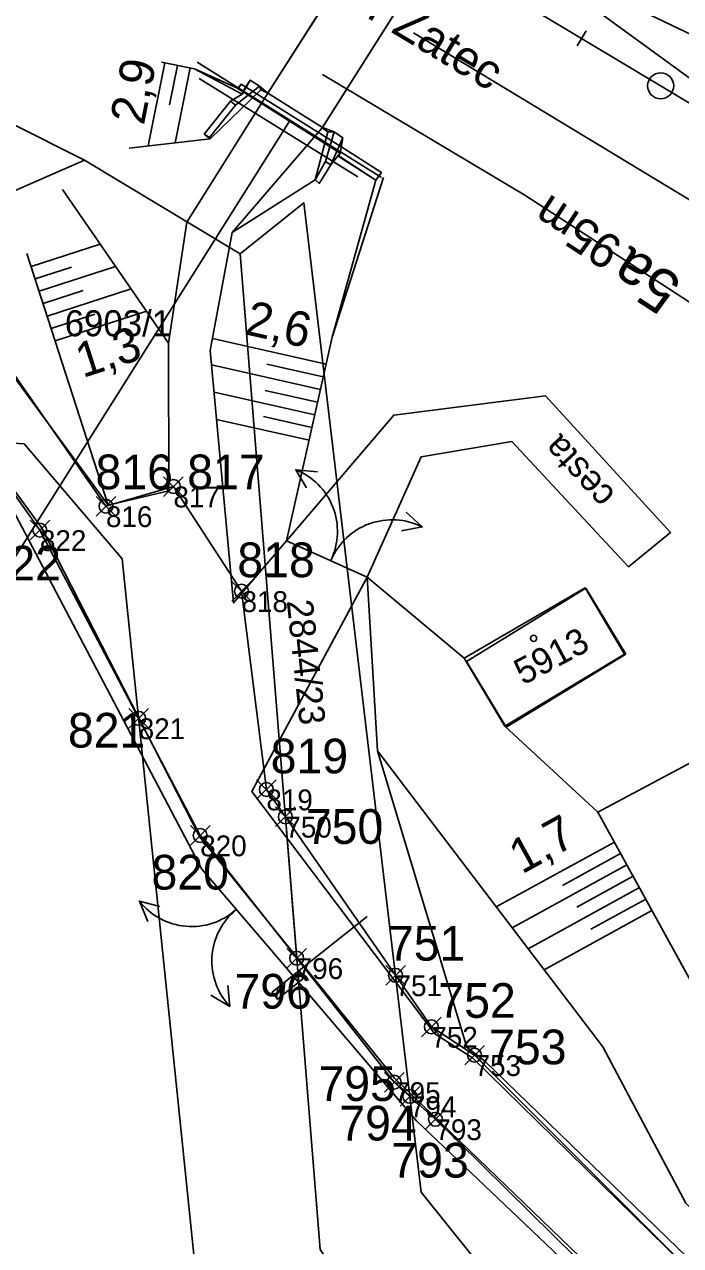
# Model space of a CAD drawing. Extents: x -800194 to -799078, y -1007177 to -1006597.
# Drawn here: x -799843.2 to -799805.4, y -1007023.9 to -1006953.5 of the extents above; entities that cross this region are included whole.
import ezdxf

# ---------------------------------------------------------------- set-up
doc = ezdxf.new("R2010")
doc.units = 0
for name, color, linetype in [('02_Osa_koleje', 7, 'Continuous'), ('_návrh', 7, 'Continuous'), ('Dočasné zábory', 7, 'Continuous'), ('Obvod stavby', 7, 'Continuous'), ('Vrstva 1', 7, 'Continuous'), ('Vrstva 17', 7, 'Continuous'), ('Vrstva 18', 7, 'Continuous'), ('Vrstva 2', 7, 'Continuous'), ('Vrstva 23', 7, 'Continuous'), ('Vrstva 4', 7, 'Continuous'), ('Vrstva 45', 7, 'Continuous'), ('Vrstva 48', 7, 'Continuous'), ('Vrstva 49', 7, 'Continuous'), ('Vrstva 51', 7, 'Continuous'), ('Vrstva 53', 7, 'Continuous'), ('Vrstva 55', 7, 'Continuous'), ('Vrstva 57', 7, 'Continuous'), ('Vrstva 59', 7, 'Continuous'), ('Vrstva 60', 7, 'Continuous'), ('Vrstva 7', 7, 'Continuous')]:
    doc.layers.add(name, color=color, linetype=linetype)

msp = doc.modelspace()

# ---------------------------------------------------------------- linework, layer by layer
at = {"layer": '_návrh'}
for p, q in [((-799820.103, -1006945.483), (-799793.935, -1006964.581)), ((-799791.771, -1006960.349), (-799809.481, -1006951.835))]:
    msp.add_line(p, q, dxfattribs=at)
for points in [[(-799821.595, -1006948.007), (-799811.064, -1006954.324), (-799803.753, -1006958.707), (-799793.935, -1006964.581), (-799784.224, -1006971.671), (-799782.913, -1006972.63), (-799767.418, -1006984.719), (-799752.333, -1006998.173), (-799735.027, -1007015.997), (-799721.623, -1007030.81), (-799713.555, -1007039.726), (-799713.111, -1007040.218)], [(-799820.755, -1006954.001), (-799803.004, -1006964.743), (-799786.682, -1006975.322), (-799769.882, -1006987.807), (-799754.745, -1007000.643), (-799736.311, -1007017.261), (-799721.623, -1007030.81)]]:
    msp.add_lwpolyline(points, dxfattribs=at)
at = {"layer": 'Dočasné zábory'}
for p, q in [((-799835.159, -1006980.715), (-799834.028, -1006979.584)), ((-799835.159, -1006979.584), (-799834.028, -1006980.715)), ((-799839.05, -1006981.851), (-799837.918, -1006980.719)), ((-799839.05, -1006980.719), (-799837.918, -1006981.851)), ((-799842.856, -1006983.229), (-799841.725, -1006982.097)), ((-799842.856, -1006982.097), (-799841.725, -1006983.229)), ((-799831.237, -1006986.747), (-799830.105, -1006985.615)), ((-799831.237, -1006985.615), (-799830.105, -1006986.747)), ((-799837.161, -1006994.075), (-799836.029, -1006992.943)), ((-799837.161, -1006992.943), (-799836.029, -1006994.075)), ((-799829.802, -1006998.175), (-799828.671, -1006997.044)), ((-799829.802, -1006997.044), (-799828.671, -1006998.175)), ((-799833.617, -1007000.824), (-799832.485, -1006999.692)), ((-799833.617, -1006999.692), (-799832.485, -1007000.824))]:
    msp.add_line(p, q, dxfattribs=at)
for points in [[(-799967.931, -1006901.133), (-799932.438, -1006916.61), (-799908.959, -1006929.954), (-799851.516, -1006962.598), (-799849.434, -1006965.582), (-799838.484, -1006981.285), (-799834.593, -1006980.15), (-799830.671, -1006986.181), (-799829.237, -1006997.609), (-799828.144, -1006999.182)], [(-799827.489, -1007007.333), (-799833.051, -1007000.258), (-799836.595, -1006993.509), (-799842.29, -1006982.663), (-799845.937, -1006977.529), (-799850.111, -1006971.653), (-799853.923, -1006967.549), (-799855.042, -1006966.345), (-799901.914, -1006939.708), (-799934.679, -1006921.088), (-799969.583, -1006905.867)]]:
    msp.add_lwpolyline(points, dxfattribs=at)
for centre in [(-799834.593, -1006980.15), (-799838.484, -1006981.285), (-799842.29, -1006982.663), (-799830.671, -1006986.181), (-799836.595, -1006993.509), (-799829.237, -1006997.609), (-799833.051, -1007000.258)]:
    msp.add_circle(centre, 0.4, dxfattribs=at)
at = {"layer": 'Obvod stavby'}
for p, q in [((-799828.709, -1006999.748), (-799827.578, -1006998.616)), ((-799828.709, -1006998.616), (-799827.578, -1006999.748)), ((-799828.055, -1007007.899), (-799826.923, -1007006.767)), ((-799828.055, -1007006.767), (-799826.923, -1007007.899)), ((-799822.359, -1007008.885), (-799821.227, -1007007.753)), ((-799822.359, -1007007.753), (-799821.227, -1007008.885)), ((-799820.294, -1007011.855), (-799819.163, -1007010.723)), ((-799820.294, -1007010.723), (-799819.163, -1007011.855)), ((-799817.801, -1007013.487), (-799816.67, -1007012.355)), ((-799817.801, -1007012.355), (-799816.67, -1007013.487)), ((-799822.436, -1007015.046), (-799821.304, -1007013.915)), ((-799822.436, -1007013.915), (-799821.304, -1007015.046)), ((-799821.531, -1007015.86), (-799820.399, -1007014.729)), ((-799821.531, -1007014.729), (-799820.399, -1007015.86)), ((-799820.06, -1007017.183), (-799818.929, -1007016.051)), ((-799820.06, -1007016.051), (-799818.929, -1007017.183))]:
    msp.add_line(p, q, dxfattribs=at)
for points in [[(-799820.965, -1007015.295), (-799821.87, -1007014.48), (-799827.489, -1007007.333), (-799828.144, -1006999.182), (-799821.793, -1007008.319)], [(-799788.573, -1007041.596), (-799817.235, -1007012.921), (-799819.729, -1007011.289), (-799821.793, -1007008.319)], [(-799820.965, -1007015.295), (-799819.494, -1007016.617), (-799797.841, -1007037.951)]]:
    msp.add_lwpolyline(points, dxfattribs=at)
for centre in [(-799828.144, -1006999.182), (-799827.489, -1007007.333), (-799821.793, -1007008.319), (-799819.729, -1007011.289), (-799817.235, -1007012.921), (-799821.87, -1007014.48), (-799820.965, -1007015.295), (-799819.494, -1007016.617)]:
    msp.add_circle(centre, 0.4, dxfattribs=at)
at = {"layer": 'Vrstva 1'}
msp.add_lwpolyline([(-799773.482, -1006996.72), (-799784.684, -1006984.939), (-799796.383, -1006975.181), (-799798.809, -1006973.435), (-799814.345, -1006963.355), (-799826.008, -1006956.394)], dxfattribs=at)
at = {"layer": 'Vrstva 17'}
for p, q in [((-799822.595, -1006962.333), (-799833.226, -1006955.692)), ((-799823.433, -1006985.376), (-799828.082, -1006983.271)), ((-799817.838, -1006990.049), (-799823.433, -1006985.376)), ((-799810.13, -1006998.908), (-799815.5, -1006993.967)), ((-799832.962, -1007002.208), (-799828.95, -1007006.881))]:
    msp.add_line(p, q, dxfattribs=at)
for points in [[(-799828.082, -1006983.271), (-799825.442, -1006971.542), (-799822.487, -1006962.331)], [(-799850.223, -1006972.842), (-799844.883, -1006979.549), (-799832.962, -1007002.208)], [(-799826.287, -1006979.308), (-799827.545, -1006979.177), (-799826.923, -1006980.227)], [(-799821.185, -1006981.617), (-799820.257, -1006982.477), (-799821.457, -1006982.702)], [(-799836.078, -1007005.216), (-799836.556, -1007004.045), (-799835.373, -1007004.348)], [(-799828.95, -1007006.881), (-799820.579, -1007016.712), (-799786.808, -1007048.821), (-799777.641, -1007052.247), (-799745.452, -1007060.292), (-799727.709, -1007066.187)], [(-799832.43, -1007009.465), (-799831.345, -1007010.115), (-799831.465, -1007008.9)]]:
    msp.add_lwpolyline(points, dxfattribs=at)
for centre, start, end in [((-799828.974, -1006982.735), 334.60495, 68.12483), ((-799821.989, -1006985.898), 63.15451, 156.67439), ((-799833.541, -1007001.676), 218.16255, 311.68243), ((-799828.546, -1007007.494), 129.61299, 223.13287)]:
    msp.add_arc(centre, 3.834, start, end, dxfattribs=at)
at = {"layer": 'Vrstva 18'}
for p, q in [((-799829.152, -1006957.479), (-799818.799, -1006941.218)), ((-799818.724, -1006941.148), (-799829.145, -1006957.469)), ((-799826.019, -1006959.481), (-799815.665, -1006943.128)), ((-799815.675, -1006943.054), (-799826.005, -1006959.461)), ((-799832.482, -1006960.109), (-799829.55, -1006957.279)), ((-799830.693, -1006956.963), (-799830.868, -1006957.21)), ((-799824.983, -1006960.928), (-799830.59, -1006957.375)), ((-799829.55, -1006957.279), (-799829.638, -1006957.076)), ((-799831.313, -1006957.935), (-799831.008, -1006958.165)), ((-799827.908, -1006959.087), (-799870.441, -1007026.562)), ((-799825.693, -1006959.713), (-799825.325, -1006959.713)), ((-799824.992, -1006960.93), (-799824.839, -1006960.052)), ((-799825.101, -1006961.073), (-799825.103, -1006961.108)), ((-799825.834, -1006961.412), (-799825.53, -1006961.608))]:
    msp.add_line(p, q, dxfattribs=at)
for points in [[(-799830.868, -1006957.21), (-799833.381, -1006956.07), (-799830.63, -1006957.53)], [(-799824.839, -1006960.052), (-799825.325, -1006959.713), (-799826.005, -1006959.461), (-799829.145, -1006957.469), (-799829.638, -1006957.076), (-799830.162, -1006956.72), (-799830.63, -1006957.53)], [(-799830.59, -1006957.375), (-799830.162, -1006956.72)], [(-799830.63, -1006957.53), (-799831.313, -1006957.935), (-799832.822, -1006959.833), (-799832.509, -1006960.04), (-799831.008, -1006958.165), (-799829.638, -1006957.076)], [(-799822.606, -1006962.05), (-799822.921, -1006962.486), (-799825.103, -1006961.108), (-799824.983, -1006960.928), (-799830.878, -1006957.218), (-799830.693, -1006956.963), (-799824.939, -1006960.553), (-799822.606, -1006962.05)], [(-799830.63, -1006957.53), (-799830.59, -1006957.375), (-799830.868, -1006957.21), (-799830.878, -1006957.218)], [(-799829.55, -1006957.279), (-799829.152, -1006957.479), (-799829.145, -1006957.469)], [(-799826.428, -1006962.473), (-799825.693, -1006959.713), (-799826.019, -1006959.481), (-799826.005, -1006959.461)], [(-799824.839, -1006960.052), (-799825.53, -1006961.608), (-799826.201, -1006962.682), (-799826.428, -1006962.473), (-799825.834, -1006961.412), (-799825.325, -1006959.713)], [(-799832.822, -1006959.833), (-799832.482, -1006960.109), (-799832.509, -1006960.04)], [(-799824.983, -1006960.928), (-799824.839, -1006960.052)], [(-799822.921, -1006962.486), (-799825.101, -1006961.073), (-799824.992, -1006960.93)], [(-799824.992, -1006960.93), (-799824.983, -1006960.928), (-799824.983, -1006960.928)]]:
    msp.add_lwpolyline(points, dxfattribs=at)
at = {"layer": 'Vrstva 2'}
msp.add_line((-799810.807, -1006953.895), (-799811.321, -1006954.753), dxfattribs=at)
at = {"layer": 'Vrstva 23'}
for points in [[(-799815.5, -1006993.967), (-799817.838, -1006990.049), (-799810.865, -1006985.994), (-799808.586, -1006989.81), (-799815.5, -1006993.967)], [(-799797.881, -1007007.005), (-799803.933, -1007010.185), (-799810.13, -1006998.908), (-799804.077, -1006995.693), (-799797.881, -1007007.005)]]:
    msp.add_lwpolyline(points, dxfattribs=at)
at = {"layer": 'Vrstva 4'}
for p, q in [((-799823.436, -1007004.934), (-799827.348, -1007008.048)), ((-799827.339, -1007008.059), (-799827.417, -1007008.742)), ((-799828.167, -1007008.7), (-799828.247, -1007009.403)), ((-799827.752, -1007008.369), (-799827.832, -1007009.072)), ((-799828.582, -1007009.03), (-799828.649, -1007009.624))]:
    msp.add_line(p, q, dxfattribs=at)
msp.add_lwpolyline([(-799827.037, -1007008.439), (-799828.601, -1007009.685), (-799828.913, -1007009.293), (-799827.348, -1007008.048)], close=True, dxfattribs=at)
at = {"layer": 'Vrstva 45'}
msp.add_line((-799823.971, -1006962.296), (-799833.117, -1006956.632), dxfattribs=at)
at = {"layer": 'Vrstva 48'}
for p, q in [((-799835.097, -1006955.728), (-799836.053, -1006960.521)), ((-799834.362, -1006955.874), (-799834.816, -1006958.153)), ((-799833.626, -1006956.021), (-799834.488, -1006960.34)), ((-799842.804, -1006967.469), (-799838.815, -1006966.177)), ((-799842.573, -1006968.182), (-799840.472, -1006967.502)), ((-799842.342, -1006968.896), (-799837.926, -1006967.466)), ((-799842.111, -1006969.609), (-799839.796, -1006968.86)), ((-799841.88, -1006970.323), (-799837.036, -1006968.755)), ((-799841.649, -1006971.036), (-799839.12, -1006970.218)), ((-799841.417, -1006971.75), (-799836.147, -1006970.043)), ((-799825.79, -1006973.09), (-799832.349, -1006971.614)), ((-799825.955, -1006973.822), (-799829.214, -1006973.088)), ((-799826.12, -1006974.553), (-799832.401, -1006973.14)), ((-799826.449, -1006976.017), (-799832.255, -1006974.71)), ((-799826.284, -1006975.285), (-799829.306, -1006974.605)), ((-799826.779, -1006977.48), (-799832.109, -1006976.28)), ((-799826.614, -1006976.748), (-799829.398, -1006976.122)), ((-799809.18, -1007000.637), (-799815.985, -1007004.377)), ((-799808.819, -1007001.295), (-799812.172, -1007003.137)), ((-799808.457, -1007001.952), (-799815.067, -1007005.584)), ((-799808.096, -1007002.609), (-799811.352, -1007004.398)), ((-799807.735, -1007003.266), (-799814.149, -1007006.791)), ((-799807.374, -1007003.924), (-799810.532, -1007005.659)), ((-799807.013, -1007004.581), (-799813.231, -1007007.998))]:
    msp.add_line(p, q, dxfattribs=at)
at = {"layer": 'Vrstva 49'}
for points in [[(-799830.63, -1006957.53), (-799833.381, -1006956.07), (-799835.276, -1006955.692)], [(-799830.63, -1006957.53), (-799831.313, -1006957.935), (-799832.822, -1006959.833), (-799832.482, -1006960.109), (-799837.146, -1006960.647)], [(-799831.126, -1006986.858), (-799832.478, -1006972.309), (-799831.215, -1006965.513), (-799826.428, -1006962.473), (-799826.201, -1006962.682), (-799825.53, -1006961.608), (-799825.101, -1006961.073), (-799822.921, -1006962.486)], [(-799822.921, -1006962.486), (-799825.442, -1006971.542), (-799828.082, -1006983.271), (-799831.126, -1006986.858)], [(-799834.851, -1006980.391), (-799834.878, -1006971.883), (-799840.982, -1006963.036)], [(-799843.049, -1006966.712), (-799838.352, -1006981.216), (-799834.851, -1006980.391)], [(-799823.433, -1006985.376), (-799817.838, -1006990.049), (-799815.5, -1006993.967), (-799810.13, -1006998.908), (-799803.933, -1007010.185), (-799801.55, -1007019.072), (-799804.246, -1007020.27), (-799789.014, -1007035.746), (-799784.101, -1007040.767), (-799778.537, -1007044.165), (-799742.314, -1007053.114), (-799725.901, -1007057.997)], [(-799823.433, -1006985.376), (-799822.824, -1006995.382), (-799809.853, -1007012.441), (-799805.067, -1007021.457), (-799784.005, -1007043.381), (-799779.029, -1007045.556), (-799742.637, -1007054.554), (-799725.892, -1007059.592)], [(-799822.824, -1006995.382), (-799817.689, -1007012.452), (-799816.629, -1007013.288), (-799784.593, -1007044.315), (-799779.066, -1007046.684), (-799743.002, -1007056.174), (-799726.202, -1007060.605)]]:
    msp.add_lwpolyline(points, dxfattribs=at)
at = {"layer": 'Vrstva 51'}
for points in [[(-799817.051, -1006918.973), (-799812.091, -1006931.542), (-799815.665, -1006943.128), (-799826.019, -1006959.481), (-799831.215, -1006965.513), (-799832.478, -1006972.309), (-799831.126, -1006986.858), (-799828.082, -1006983.271), (-799821.896, -1006976.034), (-799813.152, -1006974.923), (-799805.94, -1006982.791), (-799808.362, -1006984.771), (-799815.088, -1006977.554), (-799820.319, -1006978.428), (-799823.433, -1006985.376), (-799830.084, -1006997.726), (-799819.519, -1007011.695), (-799817.354, -1007013.08), (-799784.788, -1007044.956), (-799778.171, -1007047.694), (-799743.858, -1007056.783), (-799726.629, -1007061.89)], [(-799819.72, -1006920.416), (-799816.225, -1006931.712), (-799818.799, -1006941.218), (-799829.152, -1006957.479), (-799833.813, -1006964.907), (-799834.878, -1006971.883), (-799834.851, -1006980.391), (-799838.352, -1006981.216)], [(-799838.352, -1006981.216), (-799847.912, -1006968.244)], [(-799850.363, -1006971.39), (-799842.202, -1006982.511)], [(-799842.202, -1006982.511), (-799833.072, -1007000.361), (-799821.843, -1007014.249), (-799786.621, -1007048.212), (-799778.768, -1007050.961), (-799745.381, -1007058.848), (-799727.01, -1007064.42)]]:
    msp.add_lwpolyline(points, dxfattribs=at)
at = {"layer": 'Vrstva 53'}
msp.add_lwpolyline([(-799673.33, -1007118.14), (-799714.71, -1007110.97), (-799718.21, -1007083.69), (-799729.93, -1007087.54), (-799766.47, -1007095.84), (-799767.73, -1007094.8), (-799769.22, -1007093.56), (-799785.06, -1007080.42), (-799809.11, -1007056.81), (-799818.59, -1007034.4), (-799822.79, -1007029.13), (-799826.14, -1007024.13), (-799830.75, -1006966.73), (-799839.73, -1006961.33), (-799877.87, -1006942.17), (-799936.47, -1006903.99), (-799954.76, -1006895.45), (-799964.79, -1006890.84)], dxfattribs=at)
at = {"layer": 'Vrstva 55'}
for p, q in [((-799830.75, -1006966.73), (-799839.73, -1006961.33)), ((-799826.14, -1007024.13), (-799830.75, -1006966.73))]:
    msp.add_line(p, q, dxfattribs=at)
for points in [[(-799839.73, -1006961.33), (-799877.87, -1006942.17), (-799936.47, -1006903.99), (-799954.76, -1006895.45), (-799964.79, -1006890.84)], [(-799882.85, -1006975.35), (-799867.48, -1006973.49), (-799839.73, -1006961.33)], [(-799811.13, -1007032.26), (-799820.31, -1007020.81), (-799827.08, -1006963.79), (-799830.75, -1006966.73)], [(-799831.14, -1007046.62), (-799837.54, -1006984.31), (-799843.2, -1006977.69), (-799849.98, -1006977.29), (-799866.6, -1006981.12)], [(-799808.51, -1006989.81), (-799810.83, -1006986), (-799817.7, -1006990.24), (-799815.41, -1006994.01), (-799808.51, -1006989.81)]]:
    msp.add_lwpolyline(points, dxfattribs=at)
at = {"layer": 'Vrstva 59'}
msp.add_circle((-799813.837, -1006988.899), 0.175, dxfattribs=at)
at = {"layer": 'Vrstva 60'}
for p, q in [((-799834.593, -1006980.15), (-799834.593, -1006980.15)), ((-799838.484, -1006981.285), (-799838.484, -1006981.285)), ((-799842.29, -1006982.663), (-799842.29, -1006982.663)), ((-799830.671, -1006986.181), (-799830.671, -1006986.181)), ((-799836.595, -1006993.509), (-799836.595, -1006993.509)), ((-799829.237, -1006997.609), (-799829.237, -1006997.609)), ((-799828.144, -1006999.182), (-799828.144, -1006999.182)), ((-799833.051, -1007000.258), (-799833.051, -1007000.258)), ((-799827.489, -1007007.333), (-799827.489, -1007007.333)), ((-799821.793, -1007008.319), (-799821.793, -1007008.319)), ((-799819.729, -1007011.289), (-799819.729, -1007011.289)), ((-799817.235, -1007012.921), (-799817.235, -1007012.921)), ((-799821.87, -1007014.48), (-799821.87, -1007014.48)), ((-799820.965, -1007015.295), (-799820.965, -1007015.295)), ((-799819.495, -1007016.617), (-799819.495, -1007016.617))]:
    msp.add_line(p, q, dxfattribs=at)
at = {"layer": 'Vrstva 7'}
msp.add_circle((-799806.51, -1006957.054), 0.75, dxfattribs=at)

# ---------------------------------------------------------------- texts
at = {"layer": '02_Osa_koleje'}
msp.add_text('TÚ 0101 - směr Žatec', height=2, rotation=328.93903, dxfattribs=at).set_placement((-799838.658, -1006943.961))
at = {"layer": 'Dočasné zábory'}
for s, p in [('816', (-799839.083, -1006980.306)), ('817', (-799833.802, -1006980.306)), ('822', (-799845.54, -1006985.56)), ('818', (-799830.911, -1006985.373)), ('821', (-799840.675, -1006995.195)), ('819', (-799828.99, -1006996.679)), ('820', (-799835.86, -1007003.376))]:
    msp.add_text(s, height=2, rotation=360, dxfattribs=at).set_placement(p)
at = {"layer": 'Obvod stavby'}
for s, p in [('750', (-799826.962, -1007000.743)), ('751', (-799822.228, -1007007.475)), ('796', (-799831.076, -1007010.239)), ('752', (-799819.325, -1007010.769)), ('753', (-799816.401, -1007013.448)), ('795', (-799826.235, -1007015.56)), ('794', (-799825.033, -1007017.841)), ('793', (-799822.033, -1007019.976))]:
    msp.add_text(s, height=2, rotation=360, dxfattribs=at).set_placement(p)
at = {"layer": 'Vrstva 1'}
for s, height, p in [('95m', 2, (-799808.58, -1006966.081)), ('5a', 2.5, (-799805.164, -1006968.263))]:
    msp.add_text(s, height=height, rotation=147.02386, dxfattribs=at).set_placement(p)
at = {"layer": 'Vrstva 48'}
for s, rotation, p in [('2,9', 78.71914, (-799836.302, -1006959.367)), ('2,6', 347.31508, (-799830.553, -1006971.357)), ('1,3', 17.94412, (-799839.826, -1006973.903)), ('1,7', 28.78992, (-799814.513, -1007002.518))]:
    msp.add_text(s, height=2, rotation=rotation, dxfattribs=at).set_placement(p)
at = {"layer": 'Vrstva 51'}
msp.add_text('cesta', height=1.5, rotation=132.50913, dxfattribs=at).set_placement((-799809.061, -1006980.573))
at = {"layer": 'Vrstva 57'}
msp.add_text('6903/1', height=1.5, dxfattribs=at).set_placement((-799840.861, -1006971.488))
for s, rotation, p in [('2844/23', 276, (-799828.065, -1006986.738)), ('5913', 28, (-799814.44, -1006991.622))]:
    msp.add_text(s, height=1.5, rotation=rotation, dxfattribs=at).set_placement(p)
at = {"layer": 'Vrstva 60'}
for s, p in [('817', (-799834.593, -1006981.35)), ('816', (-799838.484, -1006982.485)), ('822', (-799842.29, -1006983.863)), ('818', (-799830.671, -1006987.381)), ('821', (-799836.595, -1006994.709)), ('819', (-799829.237, -1006998.809)), ('750', (-799828.144, -1007000.382)), ('820', (-799833.051, -1007001.458)), ('796', (-799827.489, -1007008.533)), ('751', (-799821.793, -1007009.519)), ('752', (-799819.729, -1007012.489)), ('753', (-799817.235, -1007014.121)), ('795', (-799821.87, -1007015.68)), ('794', (-799820.965, -1007016.495)), ('793', (-799819.495, -1007017.817))]:
    msp.add_text(s, height=1.2, dxfattribs=at).set_placement(p)

doc.saveas('drawing.dxf')
